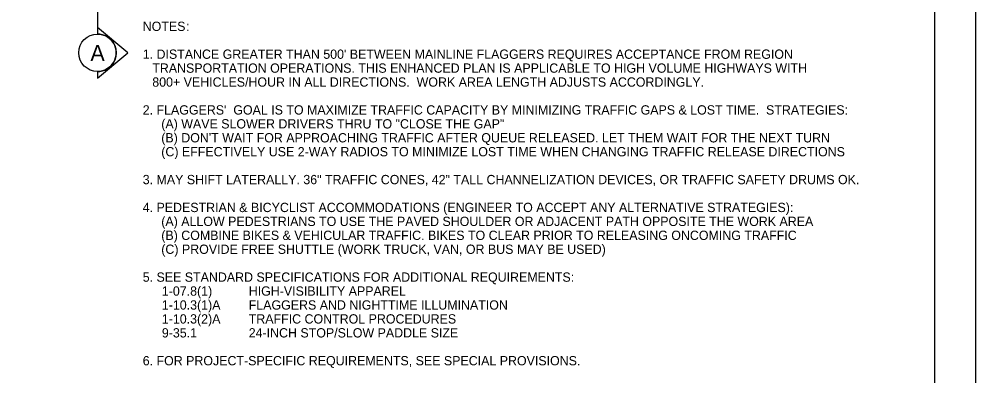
# Model space of a CAD drawing. Extents: x 99999.1 to 100095.7, y 99995 to 100010.7.
# Drawn here: x 100048.84 to 100056.06, y 100002.95 to 100005.63 of the extents above; entities that cross this region are included whole.
import ezdxf

# ---------------------------------------------------------------- set-up
doc = ezdxf.new("R2010")
doc.units = 0
for name, color, linetype in [('SH_GI_GeneralNotesBodyText', 7, 'Continuous'), ('SH_GI_PlotLimits', 7, 'Continuous'), ('SH_GI_SheetBorder', 7, 'Continuous'), ('SH_TI_WZSectionCut', 7, 'Continuous')]:
    doc.layers.add(name, color=color, linetype=linetype)

msp = doc.modelspace()

# ---------------------------------------------------------------- linework, layer by layer
at = {"layer": 'SH_GI_PlotLimits'}
msp.add_lwpolyline([(100039.0625, 99999.6875), (100056.0625, 99999.6875), (100056.0625, 100010.6875), (100039.0625, 100010.6875)], close=True, dxfattribs=at)
at = {"layer": 'SH_GI_SheetBorder'}
msp.add_line((100055.75, 100010.375), (100055.75, 100000), dxfattribs=at)
at = {"layer": 'SH_TI_WZSectionCut'}
for p, q in [((100049.4338, 100007.7022), (100049.4338, 100005.5723)), ((100049.4337, 100005.5723), (100049.4337, 100005.5224)), ((100049.6619, 100005.3812), (100049.4337, 100005.5723)), ((100049.4337, 100005.1901), (100049.6619, 100005.3812)), ((100049.4337, 100005.24), (100049.4337, 100005.1901))]:
    msp.add_line(p, q, dxfattribs=at)
msp.add_circle((100049.4338, 100005.3812), 0.1412, dxfattribs=at)
msp.add_arc((100049.4338, 100005.3812), 0.1412, 269.99779, 90.00221, dxfattribs=at)

# ---------------------------------------------------------------- texts
at = {"layer": 'SH_GI_GeneralNotesBodyText'}
for s, p in [('NOTES', (100049.7751, 100005.5456)), (':', (100050.1026, 100005.5456)), ("1. DISTANCE GREATER THAN 500' BETWEEN MAINLINE FLAGGERS REQUIRES ACCEPTANCE FROM REGION ", (100049.7751, 100005.3356)), ('TRANSPORTATION OPERATIONS. THIS ENHANCED PLAN IS APPLICABLE TO HIGH VOLUME HIGHWAYS WITH     ', (100049.8473, 100005.2306)), ('800+ VEHICLES/HOUR IN ALL DIRECTIONS.  WORK AREA LENGTH ADJUSTS ACCORDINGLY.', (100049.8473, 100005.1256)), ("2. FLAGGERS'  GOAL IS TO MAXIMIZE TRAFFIC CAPACITY BY MINIMIZING TRAFFIC GAPS & LOST TIME.  STRATEGIES:", (100049.7751, 100004.9156)), ('(A) WAVE SLOWER DRIVERS THRU TO "CLOSE THE GAP"', (100049.9151, 100004.8106)), ("(B) DON'T WAIT FOR APPROACHING TRAFFIC AFTER QUEUE RELEASED. LET THEM WAIT FOR THE NEXT TURN", (100049.9151, 100004.7056)), ('(C) EFFECTIVELY USE 2-WAY RADIOS TO MINIMIZE LOST TIME WHEN CHANGING TRAFFIC RELEASE DIRECTIONS', (100049.9151, 100004.6006)), ('3. MAY SHIFT LATERALLY. 36" TRAFFIC CONES, 42" TALL CHANNELIZATION DEVICES, OR TRAFFIC SAFETY DRUMS OK.', (100049.7751, 100004.3906)), ('4. PEDESTRIAN & BICYCLIST ACCOMMODATIONS (ENGINEER TO ACCEPT ANY ALTERNATIVE STRATEGIES):', (100049.7751, 100004.1806)), ('(A) ALLOW PEDESTRIANS TO USE THE PAVED SHOULDER OR ADJACENT PATH OPPOSITE THE WORK AREA', (100049.9151, 100004.0756)), ('(B) COMBINE BIKES & VEHICULAR TRAFFIC. BIKES TO CLEAR PRIOR TO RELEASING ONCOMING TRAFFIC', (100049.9151, 100003.9706)), ('(C) PROVIDE FREE SHUTTLE (WORK TRUCK, VAN, OR BUS MAY BE USED)', (100049.9151, 100003.8656)), ('5. SEE STANDARD SPECIFICATIONS FOR ADDITIONAL REQUIREMENTS:', (100049.7751, 100003.6556)), ('1-07.8(1) ', (100049.9195, 100003.5506)), ('HIGH-VISIBILITY APPAREL', (100050.5751, 100003.5506)), ('1-10.3(1)A ', (100049.9195, 100003.4456)), ('FLAGGERS AND NIGHTTIME ILLUMINATION', (100050.5751, 100003.4456)), ('1-10.3(2)A', (100049.9195, 100003.3406)), ('TRAFFIC CONTROL PROCEDURES', (100050.5751, 100003.3406)), ('9-35.1', (100049.9195, 100003.2356)), ('24-INCH STOP/SLOW PADDLE SIZE', (100050.5751, 100003.2356)), ('6. FOR PROJECT-SPECIFIC REQUIREMENTS, SEE SPECIAL PROVISIONS.', (100049.7751, 100003.0256))]:
    msp.add_text(s, height=0.07, rotation=360, dxfattribs=at).set_placement(p)
at = {"layer": 'SH_TI_WZSectionCut'}
msp.add_text('A', height=0.12, rotation=0.00995, dxfattribs=at).set_placement((100049.3808, 100005.3203))

doc.saveas('drawing.dxf')
